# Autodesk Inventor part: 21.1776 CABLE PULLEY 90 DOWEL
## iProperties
Created: 2007-05
Part Number: 21.1776 CABLE PULLEY 90 DOWEL
Material: Steel
Document SubType Name: Modeling
Designer: Andy Moles
Density: 7.85 g/cm^3
Mass: 13.5449 g
Surface Area: 11.893 cm^2
Volume: 1.72547 cm^3
Author: Andy Moles
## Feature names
1. Extrusion1
2. Fillet1
